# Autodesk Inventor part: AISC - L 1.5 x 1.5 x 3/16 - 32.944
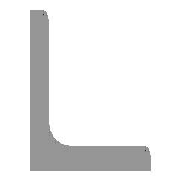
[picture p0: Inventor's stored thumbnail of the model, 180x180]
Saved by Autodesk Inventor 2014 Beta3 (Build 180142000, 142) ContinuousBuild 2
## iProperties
IsCustomPart: 1
Created: 2010-11
Part Number: AISC - L 1.5 x 1.5 x 3/16 - 32.944
Material: Steel, Mild
Description: Angle Steel
Document SubType Name: Modeling
Standard: ANSI
Designer: Beta-8540w
Standards Organization: ANSI
Language: en-US
Size Designation: L 1.5 x 1.5 x 3/16
Categories: <MemberInstance><Categories><Category DisplayName="Structural Shapes" InternalName="089c4875-fa83-4c05-b084-43b9cc11f5ed" Mnemonic="GRDR"><CategoryParameter Dis
Stock Number: L 1.5 x 1.5 x 3/16
Density: 7.86 g/cm^3
Appearance: Steel
G_L: 32.944 in
G_W: 1.500 in
G_H: 1.500 in
_CCFamilyMember: 5
_CCFamilyDisplayName: ANSI L (Equal angles) - Angle Steel
_FrameMemberDoc: Frame Member File
_Version: 15.0.0
_GetPNFromCC: 1
Author: Beta-8540w
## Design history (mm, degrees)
node "Start plane"
node "End plane"
sketch "Sketch"
  geometry: L1 (38.1, 0)-(0, 0); L2 (0, 0)-(0, 38.1); L3 (0, 38.1)-(2.476, 38.1); L4 (4.762, 35.814)-(4.762, 9.589); L5 (9.588, 4.763)-(35.814, 4.763); L6 (38.1, 2.477)-(38.1, 0); L7 (0, -11.041)-(0, 31.538); L8 (-11.041, 0)-(31.538, 0); L9 (0, 48.496)-(0, -20.964) reference; L10 (-20.964, 0)-(48.496, 0) reference; A1 r 4.826 centre (9.588, 9.589) between (4.762, 9.589) and (9.588, 4.763); A2 r 2.286 centre (2.476, 35.814) between (4.762, 35.814) and (2.476, 38.1); A3 r 2.286 centre (35.814, 2.477) between (38.1, 2.477) and (35.814, 4.763); 3 further points
  constraints: 16 end point, 6 point on circle, 6 point on line, 6 tangent, 4 parallel, 3 centre point, 2 collinear, 1 equal radius, 1 horizontal, 1 perpendicular
  dimensions: "d0" = 38.1 distance between parallel lines of L6 L2 (= G_H); "d1" = 38.1 distance between parallel lines of L3 L1 (= G_H); "d2" = 4.7625 distance between parallel lines of L2 L4 (= G_T); "d3" = 4.7625 distance between parallel lines of L1 L5 (= G_T); "d10" = 0 distance between parallel lines of L7 L2 (computed from ex); "d11" = 0 distance between parallel lines of L8 L1 (computed from d10); "d14" = 4.826 radius of A1 (= G_IR); "d15" = 2.286 radius of A2 (= G_ER)
extrude "Body" new body sketch "Sketch" stored distance "d4" = 836.76542 (= G_L); taper "d5" = 0 deg
node "Driven Length"
  sketch "Sketch3"
    geometry: L1 (0, 0)-(10, 0) reference
    constraints: 2 end point, 1 horizontal
  workplane "Work Plane3"
  sketch "Sketch4"
    geometry: L1 (-2, 0)-(12, 0) reference; L2 (-2, 836.765)-(12, 836.765) reference
    dimensions: "d17" = 836.76542 distance between parallel lines of L1 L2 (derived)
body "Solid1"
other parameters: "G_H" = 38.1 [user parameter; used in 2 equation terms], "G_T" = 4.7625 [user parameter; used in 2 equation terms], "G_ER" = 2.286 [user parameter; used in 1 equation term], "G_IR" = 4.826 [user parameter; used in 1 equation term], "G_L" = 836.76542 (= d17) [user parameter; used in 1 equation term], "ex" = 0 [user parameter; used in 1 equation term], "G_OFFSET_START" = 0 [user parameter; used in 1 equation term], "G_OFFSET_END" = 0 [user parameter; used in 1 equation term], "d12" = 0 (computed from G_OFFSET_START), "d13" = 836.76542 (= G_OFFSET_END + B_L), "B_L" = 836.76542 [user parameter; used in 1 equation term], "d16" = 90 deg, "MAS" = 0.26787 [user parameter]
